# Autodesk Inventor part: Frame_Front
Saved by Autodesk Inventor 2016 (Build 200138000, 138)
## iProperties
Created: 2015-11
Part Number: Frame_Front
Material: Generic
Document SubType Name: Modeling
Designer: John
Density: 1 g/cm^3
Appearance: Default
Author: John
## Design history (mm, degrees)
feature "SOLID1"
body "Solid1"
